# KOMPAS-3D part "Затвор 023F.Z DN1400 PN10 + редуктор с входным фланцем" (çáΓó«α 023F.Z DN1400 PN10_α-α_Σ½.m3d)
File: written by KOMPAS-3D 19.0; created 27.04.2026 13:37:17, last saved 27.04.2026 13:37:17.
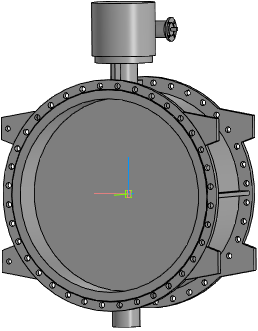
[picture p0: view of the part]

Document properties: Полное имя файла: ..\..\Затвор 023F.Z DN200-DN1600_редуктор с входным фланцем\Затвор 023F.Z DN1400 PN10 + редуктор с входным фланцем.a3d

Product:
- Part/product: Затвор 023F.Z DN1400 PN10 + редуктор с входным фланцем
    Масса: 3312.39

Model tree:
1. Операция без истории:1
